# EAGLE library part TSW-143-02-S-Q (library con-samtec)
THROUGH-HOLE .025" SQ POST HEADER Source: Samtec TSW.pdf
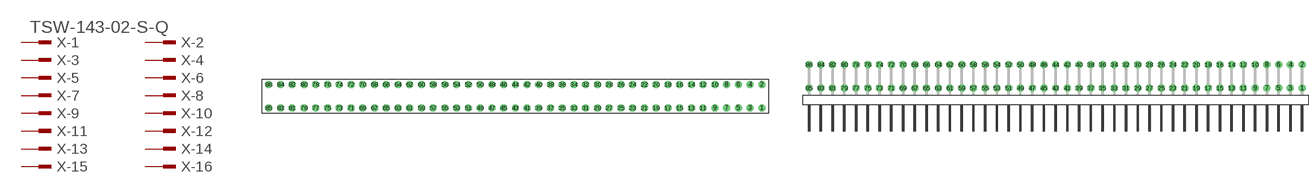
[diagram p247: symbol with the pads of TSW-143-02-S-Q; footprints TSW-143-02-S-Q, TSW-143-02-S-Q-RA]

Designator prefix X; gates -1=MPINV -2=MPIN -3=MPIN -4=MPIN -5=MPIN -6=MPIN -7=MPIN -8=MPIN -9=MPIN -10=MPIN -11=MPIN -12=MPIN -13=MPIN -14=MPIN -15=MPIN -16=MPIN -17=MPIN -18=MPIN -19=MPIN -20=MPIN -21=MPIN -22=MPIN -23=MPIN -24=MPIN -25=MPIN -26=MPIN -27=MPIN -28=MPIN -29=MPIN -30=MPIN -31=MPIN -32=MPIN -33=MPIN -34=MPIN -35=MPIN -36=MPIN -37=MPIN -38=MPIN -39=MPIN -40=MPIN -41=MPIN -42=MPIN -43=MPIN -44=MPIN -45=MPIN -46=MPIN -47=MPIN -48=MPIN -49=MPIN -50=MPIN -51=MPIN -52=MPIN -53=MPIN -54=MPIN -55=MPIN -56=MPIN -57=MPIN -58=MPIN -59=MPIN -60=MPIN -61=MPIN -62=MPIN -63=MPIN -64=MPIN -65=MPIN -66=MPIN -67=MPIN -68=MPIN -69=MPIN -70=MPIN -71=MPIN -72=MPIN -73=MPIN -74=MPIN -75=MPIN -76=MPIN -77=MPIN -78=MPIN -79=MPIN -80=MPIN -81=MPIN -82=MPIN -83=MPIN -84=MPIN -85=MPIN -86=MPIN

## TSW-143-02-S-Q (OC_FARNELL: unknown; OC_NEWARK: unknown)  [TSW-143-02-S-Q]
1  -1:1  pas
2  -2:1  pas
3  -3:1  pas
4  -4:1  pas
5  -5:1  pas
6  -6:1  pas
7  -7:1  pas
8  -8:1  pas
9  -9:1  pas
10  -10:1  pas
11  -11:1  pas
12  -12:1  pas
13  -13:1  pas
14  -14:1  pas
15  -15:1  pas
16  -16:1  pas
17  -17:1  pas
18  -18:1  pas
19  -19:1  pas
20  -20:1  pas
21  -21:1  pas
22  -22:1  pas
23  -23:1  pas
24  -24:1  pas
25  -25:1  pas
26  -26:1  pas
27  -27:1  pas
28  -28:1  pas
29  -29:1  pas
30  -30:1  pas
31  -31:1  pas
32  -32:1  pas
33  -33:1  pas
34  -34:1  pas
35  -35:1  pas
36  -36:1  pas
37  -37:1  pas
38  -38:1  pas
39  -39:1  pas
40  -40:1  pas
41  -41:1  pas
42  -42:1  pas
43  -43:1  pas
44  -44:1  pas
45  -45:1  pas
46  -46:1  pas
47  -47:1  pas
48  -48:1  pas
49  -49:1  pas
50  -50:1  pas
51  -51:1  pas
52  -52:1  pas
53  -53:1  pas
54  -54:1  pas
55  -55:1  pas
56  -56:1  pas
57  -57:1  pas
58  -58:1  pas
59  -59:1  pas
60  -60:1  pas
61  -61:1  pas
62  -62:1  pas
63  -63:1  pas
64  -64:1  pas
65  -65:1  pas
66  -66:1  pas
67  -67:1  pas
68  -68:1  pas
69  -69:1  pas
70  -70:1  pas
71  -71:1  pas
72  -72:1  pas
73  -73:1  pas
74  -74:1  pas
75  -75:1  pas
76  -76:1  pas
77  -77:1  pas
78  -78:1  pas
79  -79:1  pas
80  -80:1  pas
81  -81:1  pas
82  -82:1  pas
83  -83:1  pas
84  -84:1  pas
85  -85:1  pas
86  -86:1  pas

## TSW-143-02-S-Q-RA (OC_FARNELL: unknown; OC_NEWARK: unknown)  [TSW-143-02-S-Q-RA]
Pads as for TSW-143-02-S-Q

## Footprint TSW-143-02-S-Q (pad centres in mm)
THROUGH-HOLE .025" SQ POST HEADER Source: Samtec TSW.pdf
drill 1 pad 1.5 octagon: 1 53.34,-2.54; 2 53.34,2.54; 3 50.8,-2.54; 4 50.8,2.54; 5 48.26,-2.54; 6 48.26,2.54; 7 45.72,-2.54; 8 45.72,2.54; 9 43.18,-2.54; 10 43.18,2.54; 11 40.64,-2.54; 12 40.64,2.54; 13 38.1,-2.54; 14 38.1,2.54; 15 35.56,-2.54; 16 35.56,2.54; 17 33.02,-2.54; 18 33.02,2.54; 19 30.48,-2.54; 20 30.48,2.54; 21 27.94,-2.54; 22 27.94,2.54; 23 25.4,-2.54; 24 25.4,2.54; 25 22.86,-2.54; 26 22.86,2.54; 27 20.32,-2.54; 28 20.32,2.54; 29 17.78,-2.54; 30 17.78,2.54; 31 15.24,-2.54; 32 15.24,2.54; 33 12.7,-2.54; 34 12.7,2.54; 35 10.16,-2.54; 36 10.16,2.54; 37 7.62,-2.54; 38 7.62,2.54; 39 5.08,-2.54; 40 5.08,2.54; 41 2.54,-2.54; 42 2.54,2.54; 43 0,-2.54; 44 0,2.54; 45 -2.54,-2.54; 46 -2.54,2.54; 47 -5.08,-2.54; 48 -5.08,2.54; 49 -7.62,-2.54; 50 -7.62,2.54; 51 -10.16,-2.54; 52 -10.16,2.54; 53 -12.7,-2.54; 54 -12.7,2.54; 55 -15.24,-2.54; 56 -15.24,2.54; 57 -17.78,-2.54; 58 -17.78,2.54; 59 -20.32,-2.54; 60 -20.32,2.54; 61 -22.86,-2.54; 62 -22.86,2.54; 63 -25.4,-2.54; 64 -25.4,2.54; 65 -27.94,-2.54; 66 -27.94,2.54; 67 -30.48,-2.54; 68 -30.48,2.54; 69 -33.02,-2.54; 70 -33.02,2.54; 71 -35.56,-2.54; 72 -35.56,2.54; 73 -38.1,-2.54; 74 -38.1,2.54; 75 -40.64,-2.54; 76 -40.64,2.54; 77 -43.18,-2.54; 78 -43.18,2.54; 79 -45.72,-2.54; 80 -45.72,2.54; 81 -48.26,-2.54; 82 -48.26,2.54; 83 -50.8,-2.54; 84 -50.8,2.54; 85 -53.34,-2.54; 86 -53.34,2.54

## Footprint TSW-143-02-S-Q-RA (pad centres in mm)
THROUGH-HOLE .025" SQ POST HEADER Source: Samtec TSW.pdf
drill 1 pad 1.5 octagon: 1 53.34,1.524; 2 53.34,6.604; 3 50.8,1.524; 4 50.8,6.604; 5 48.26,1.524; 6 48.26,6.604; 7 45.72,1.524; 8 45.72,6.604; 9 43.18,1.524; 10 43.18,6.604; 11 40.64,1.524; 12 40.64,6.604; 13 38.1,1.524; 14 38.1,6.604; 15 35.56,1.524; 16 35.56,6.604; 17 33.02,1.524; 18 33.02,6.604; 19 30.48,1.524; 20 30.48,6.604; 21 27.94,1.524; 22 27.94,6.604; 23 25.4,1.524; 24 25.4,6.604; 25 22.86,1.524; 26 22.86,6.604; 27 20.32,1.524; 28 20.32,6.604; 29 17.78,1.524; 30 17.78,6.604; 31 15.24,1.524; 32 15.24,6.604; 33 12.7,1.524; 34 12.7,6.604; 35 10.16,1.524; 36 10.16,6.604; 37 7.62,1.524; 38 7.62,6.604; 39 5.08,1.524; 40 5.08,6.604; 41 2.54,1.524; 42 2.54,6.604; 43 0,1.524; 44 0,6.604; 45 -2.54,1.524; 46 -2.54,6.604; 47 -5.08,1.524; 48 -5.08,6.604; 49 -7.62,1.524; 50 -7.62,6.604; 51 -10.16,1.524; 52 -10.16,6.604; 53 -12.7,1.524; 54 -12.7,6.604; 55 -15.24,1.524; 56 -15.24,6.604; 57 -17.78,1.524; 58 -17.78,6.604; 59 -20.32,1.524; 60 -20.32,6.604; 61 -22.86,1.524; 62 -22.86,6.604; 63 -25.4,1.524; 64 -25.4,6.604; 65 -27.94,1.524; 66 -27.94,6.604; 67 -30.48,1.524; 68 -30.48,6.604; 69 -33.02,1.524; 70 -33.02,6.604; 71 -35.56,1.524; 72 -35.56,6.604; 73 -38.1,1.524; 74 -38.1,6.604; 75 -40.64,1.524; 76 -40.64,6.604; 77 -43.18,1.524; 78 -43.18,6.604; 79 -45.72,1.524; 80 -45.72,6.604; 81 -48.26,1.524; 82 -48.26,6.604; 83 -50.8,1.524; 84 -50.8,6.604; 85 -53.34,1.524; 86 -53.34,6.604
